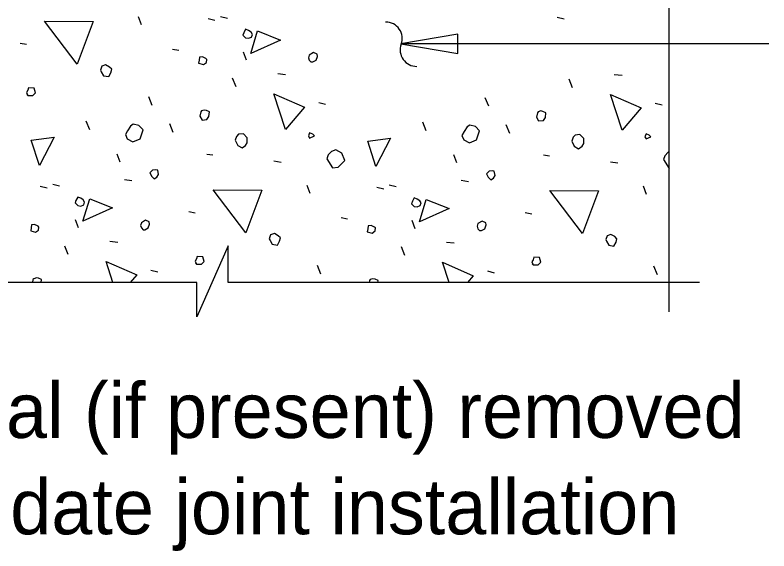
# Model space of a CAD drawing. Extents: x -7.9 to 27, y -3.1 to 14.6.
# Drawn here: x 4.546 to 5.578, y 2.374 to 3.108 of the extents above; entities that cross this region are included whole.
import ezdxf

# ---------------------------------------------------------------- set-up
doc = ezdxf.new("R2010")
doc.units = 0
doc.layers.add('PlotBorder_dp', color=7, linetype='Continuous')
doc.layers.add('TextMisc', color=7, linetype='Continuous')

msp = doc.modelspace()

# ---------------------------------------------------------------- linework, layer by layer
at = {"layer": 'PlotBorder_dp'}
msp.add_line((5.5781, 3.0683), (5.074, 3.0683), dxfattribs=at)
for points in [[(5.4416, 2.7012), (5.4416, 3.3364), (5.4918, 3.3364), (5.3945, 3.3796), (5.4416, 3.3796), (5.4416, 3.9158)], [(5.483, 2.7414), (4.8378, 2.7414), (4.8378, 2.7916), (4.7947, 2.6944), (4.7947, 2.7414), (4.2194, 2.7414)]]:
    msp.add_lwpolyline(points, dxfattribs=at)
msp.add_lwpolyline([(5.0739, 3.0683), (5.152, 3.055), (5.152, 3.0815)], close=True, dxfattribs=at)
for centre, start, end in [((5.0537, 3.0758), 339.2893, 91.0165), ((5.0956, 3.06), 159.2893, 271.0165)]:
    msp.add_arc(centre, 0.0224, start, end, dxfattribs=at)
at = {"layer": 'TextMisc'}
for p, q in [((4.7188, 3.0943), (4.7147, 3.1055)), ((4.8102, 3.1032), (4.8196, 3.1008)), ((4.8273, 3.1061), (4.8367, 3.1037)), ((5.2881, 3.1049), (5.2975, 3.1026)), ((4.5527, 3.0696), (4.5615, 3.0678)), ((4.7613, 3.0613), (4.7701, 3.0596)), ((4.8626, 3.046), (4.8585, 3.0572)), ((4.9056, 3.0277), (4.9162, 3.0266)), ((5.3664, 3.0266), (5.377, 3.0254)), ((4.8485, 3.0095), (4.8438, 3.0213)), ((5.3093, 3.0083), (5.3046, 3.0201)), ((4.7336, 2.9841), (4.7289, 2.9959)), ((5.1944, 2.983), (5.1897, 2.9947)), ((4.9616, 2.9883), (4.971, 2.9859)), ((5.4224, 2.9871), (5.4318, 2.9847)), ((4.6481, 2.9505), (4.6434, 2.9623)), ((4.7625, 2.947), (4.7577, 2.9588)), ((5.1089, 2.9494), (5.1042, 2.9611)), ((5.2232, 2.9458), (5.2185, 2.9576)), ((4.69, 2.9063), (4.6858, 2.9175)), ((4.8084, 2.9175), (4.8167, 2.9164)), ((5.1508, 2.9052), (5.1466, 2.9164)), ((5.2692, 2.9164), (5.2775, 2.9152)), ((4.9003, 2.9081), (4.9104, 2.9063)), ((5.3611, 2.9069), (5.3712, 2.9052)), ((4.6959, 2.8828), (4.7059, 2.881)), ((5.1567, 2.8816), (5.1667, 2.8798)), ((4.5804, 2.8734), (4.5898, 2.871)), ((4.5975, 2.8763), (4.6069, 2.8739)), ((4.9498, 2.8633), (4.9457, 2.8745)), ((5.0412, 2.8722), (5.0506, 2.8698)), ((5.0583, 2.8751), (5.0677, 2.8728)), ((5.4106, 2.8622), (5.4065, 2.8734)), ((4.7837, 2.8386), (4.7925, 2.8368)), ((4.9923, 2.8303), (5.0011, 2.8286)), ((5.2445, 2.8374), (5.2533, 2.8356)), ((4.6328, 2.8162), (4.6287, 2.8274)), ((5.0936, 2.815), (5.0895, 2.8262)), ((4.6758, 2.7979), (4.6864, 2.7967)), ((4.6187, 2.7797), (4.614, 2.7914)), ((5.0795, 2.7785), (5.0748, 2.7903)), ((5.1366, 2.7967), (5.1472, 2.7956)), ((4.7318, 2.7584), (4.7412, 2.7561)), ((4.9646, 2.7531), (4.9599, 2.7649)), ((5.1926, 2.7573), (5.202, 2.7549)), ((5.4254, 2.752), (5.4206, 2.7637))]:
    msp.add_line(p, q, dxfattribs=at)
for points in [[(4.631, 3.0407), (4.5863, 3.0996), (4.6528, 3.099), (4.631, 3.0407)], [(4.8614, 3.0766), (4.8656, 3.0761), (4.8697, 3.0778), (4.8709, 3.0814), (4.8691, 3.0843), (4.8656, 3.0867), (4.8614, 3.0884), (4.8591, 3.0837), (4.8579, 3.0802), (4.8614, 3.0766)], [(4.8685, 3.0554), (4.8779, 3.0861), (4.9092, 3.0737), (4.8685, 3.0554)], [(4.951, 3.0436), (4.9534, 3.0436), (4.9581, 3.046), (4.9599, 3.0513), (4.9593, 3.0543), (4.9545, 3.0566), (4.9487, 3.0531), (4.9475, 3.0495), (4.9487, 3.046), (4.951, 3.0436)], [(4.7972, 3.0419), (4.8037, 3.0401), (4.8078, 3.0431), (4.8084, 3.0472), (4.8072, 3.0484), (4.8025, 3.0507), (4.7984, 3.0501), (4.7978, 3.046), (4.7972, 3.0419)], [(4.664, 3.0301), (4.667, 3.0248), (4.6741, 3.0236), (4.677, 3.0289), (4.6782, 3.0336), (4.6752, 3.0366), (4.6699, 3.0395), (4.6646, 3.0378), (4.6629, 3.0324), (4.664, 3.0301)], [(4.5633, 2.9977), (4.5704, 2.9977), (4.5739, 3.0012), (4.5721, 3.0077), (4.5645, 3.0083), (4.5633, 3.0048), (4.5615, 3.0018), (4.5633, 2.9977), (4.5621, 2.9989)], [(4.9162, 2.9511), (4.9003, 3), (4.9422, 2.9818), (4.9162, 2.9511)], [(5.377, 2.95), (5.3611, 2.9989), (5.403, 2.9806), (5.377, 2.95)], [(4.799, 2.9694), (4.8019, 2.9641), (4.8084, 2.9647), (4.8114, 2.9688), (4.8119, 2.9753), (4.8078, 2.9771), (4.8049, 2.9776), (4.8013, 2.9765), (4.8002, 2.9753), (4.799, 2.9694)], [(5.2598, 2.9682), (5.2627, 2.9629), (5.2692, 2.9635), (5.2722, 2.9676), (5.2727, 2.9741), (5.2686, 2.9759), (5.2657, 2.9765), (5.2621, 2.9753), (5.261, 2.9741), (5.2598, 2.9682)], [(4.6994, 2.9382), (4.7071, 2.934), (4.7171, 2.9382), (4.7212, 2.9505), (4.7153, 2.9564), (4.7076, 2.9582), (4.7041, 2.9558), (4.7, 2.9494), (4.697, 2.9441), (4.6994, 2.9382)], [(5.1602, 2.937), (5.1679, 2.9329), (5.1779, 2.937), (5.182, 2.9494), (5.1761, 2.9553), (5.1684, 2.957), (5.1649, 2.9547), (5.1608, 2.9482), (5.1578, 2.9429), (5.1602, 2.937)], [(4.8473, 2.9364), (4.8508, 2.9293), (4.8567, 2.9258), (4.8614, 2.9293), (4.8638, 2.9329), (4.8638, 2.9399), (4.8585, 2.9452), (4.852, 2.9447), (4.8491, 2.9417), (4.8473, 2.9364)], [(4.9492, 2.9393), (4.9557, 2.9423), (4.9534, 2.9447), (4.9492, 2.9464), (4.9475, 2.9423), (4.9492, 2.9393)], [(5.3081, 2.9352), (5.3116, 2.9282), (5.3175, 2.9246), (5.3222, 2.9282), (5.3246, 2.9317), (5.3246, 2.9388), (5.3193, 2.9441), (5.3128, 2.9435), (5.3099, 2.9405), (5.3081, 2.9352)], [(5.41, 2.9382), (5.4165, 2.9411), (5.4142, 2.9435), (5.41, 2.9452), (5.4083, 2.9411), (5.41, 2.9382)], [(4.5792, 2.9016), (4.568, 2.9364), (4.5992, 2.9405), (4.5792, 2.9016)], [(5.04, 2.9005), (5.0288, 2.9352), (5.06, 2.9393), (5.04, 2.9005)], [(4.9728, 2.9111), (4.9805, 2.8987), (4.9881, 2.8993), (4.9911, 2.9022), (4.9976, 2.9087), (4.9934, 2.9187), (4.9852, 2.9234), (4.9793, 2.9211), (4.9746, 2.9164), (4.9728, 2.9111)], [(5.4416, 2.9205), (5.4401, 2.9199), (5.4354, 2.9152), (5.4336, 2.9099)], [(5.4336, 2.9099), (5.4413, 2.8975), (5.4416, 2.8975)], [(4.733, 2.8869), (4.7365, 2.8834), (4.7401, 2.8857), (4.7424, 2.8893), (4.7412, 2.8952), (4.7383, 2.8957), (4.7342, 2.8952), (4.7306, 2.8916), (4.733, 2.8869)], [(5.1938, 2.8857), (5.1973, 2.8822), (5.2009, 2.8845), (5.2032, 2.8881), (5.202, 2.894), (5.1991, 2.8946), (5.195, 2.894), (5.1914, 2.8904), (5.1938, 2.8857)], [(4.862, 2.8097), (4.8173, 2.8686), (4.8838, 2.868), (4.862, 2.8097)], [(5.3228, 2.8085), (5.278, 2.8675), (5.3446, 2.8669), (5.3228, 2.8085)], [(4.6316, 2.8468), (4.6358, 2.8462), (4.6399, 2.848), (4.6411, 2.8515), (4.6393, 2.8545), (4.6358, 2.8569), (4.6316, 2.8586), (4.6293, 2.8539), (4.6281, 2.8504), (4.6316, 2.8468)], [(4.6387, 2.8256), (4.6481, 2.8563), (4.6794, 2.8439), (4.6387, 2.8256)], [(5.0924, 2.8457), (5.0966, 2.8451), (5.1007, 2.8468), (5.1019, 2.8504), (5.1001, 2.8533), (5.0966, 2.8557), (5.0924, 2.8574), (5.0901, 2.8527), (5.0889, 2.8492), (5.0924, 2.8457)], [(5.0995, 2.8244), (5.1089, 2.8551), (5.1402, 2.8427), (5.0995, 2.8244)], [(4.5674, 2.8121), (4.5739, 2.8103), (4.578, 2.8132), (4.5786, 2.8174), (4.5774, 2.8185), (4.5727, 2.8209), (4.5686, 2.8203), (4.568, 2.8162), (4.5674, 2.8121)], [(4.7212, 2.8138), (4.7236, 2.8138), (4.7283, 2.8162), (4.73, 2.8215), (4.7295, 2.8244), (4.7247, 2.8268), (4.7188, 2.8233), (4.7177, 2.8197), (4.7188, 2.8162), (4.7212, 2.8138)], [(5.0282, 2.8109), (5.0347, 2.8091), (5.0388, 2.8121), (5.0394, 2.8162), (5.0382, 2.8174), (5.0335, 2.8197), (5.0294, 2.8191), (5.0288, 2.815), (5.0282, 2.8109)], [(5.182, 2.8127), (5.1844, 2.8127), (5.1891, 2.815), (5.1908, 2.8203), (5.1903, 2.8233), (5.1855, 2.8256), (5.1796, 2.8221), (5.1785, 2.8185), (5.1796, 2.815), (5.182, 2.8127)], [(4.895, 2.7991), (4.898, 2.7938), (4.9051, 2.7926), (4.908, 2.7979), (4.9092, 2.8026), (4.9062, 2.8056), (4.9009, 2.8085), (4.8956, 2.8068), (4.8939, 2.8015), (4.895, 2.7991)], [(5.3558, 2.7979), (5.3588, 2.7926), (5.3658, 2.7914), (5.3688, 2.7967), (5.37, 2.8015), (5.367, 2.8044), (5.3617, 2.8074), (5.3564, 2.8056), (5.3547, 2.8003), (5.3558, 2.7979)], [(4.7943, 2.7667), (4.8013, 2.7667), (4.8049, 2.7702), (4.8031, 2.7767), (4.7954, 2.7773), (4.7943, 2.7738), (4.7925, 2.7708), (4.7943, 2.7667), (4.7931, 2.7679)], [(4.6799, 2.7415), (4.6705, 2.7702), (4.7124, 2.752), (4.7035, 2.7415)], [(5.1403, 2.7415), (5.1313, 2.7691), (5.1732, 2.7508), (5.1653, 2.7415)], [(5.2551, 2.7655), (5.2621, 2.7655), (5.2657, 2.7691), (5.2639, 2.7755), (5.2562, 2.7761), (5.2551, 2.7726), (5.2533, 2.7696), (5.2551, 2.7655), (5.2539, 2.7667)], [(4.5818, 2.7415), (4.5821, 2.7455), (4.578, 2.7472), (4.5751, 2.7478), (4.5715, 2.7467), (4.5704, 2.7455), (4.5696, 2.7415)], [(5.0427, 2.7415), (5.0429, 2.7443), (5.0388, 2.7461), (5.0359, 2.7467), (5.0323, 2.7455), (5.0312, 2.7443), (5.0306, 2.7415)]]:
    msp.add_lwpolyline(points, dxfattribs=at)

# ---------------------------------------------------------------- texts
at = {"layer": 'PlotBorder_dp'}
for s, p in [('Form Material (if present) removed ', (3.9887, 2.5285)), ('to accommodate joint installation', (3.9887, 2.3965))]:
    msp.add_text(s, height=0.0756, dxfattribs=at).set_placement(p)

doc.saveas('drawing.dxf')
